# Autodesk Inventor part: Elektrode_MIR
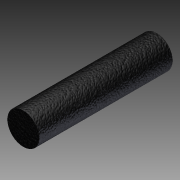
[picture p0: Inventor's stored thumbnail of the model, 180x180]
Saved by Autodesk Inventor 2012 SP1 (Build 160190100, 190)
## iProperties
Created: 2012-10
Part Number: Elektrode_MIR
Material: Default
Document SubType Name: Modeling
Designer: Dominic Mähling
Density: 1 g/cm^3
Author: Dominic Mähling
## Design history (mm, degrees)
derived "Elektrode.ipt"
feature "Volumenkörper1::Elektrode.ipt" dims "d0" = 10
tag "Bezeichnung1"
node "Volumenkörper1"
